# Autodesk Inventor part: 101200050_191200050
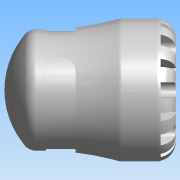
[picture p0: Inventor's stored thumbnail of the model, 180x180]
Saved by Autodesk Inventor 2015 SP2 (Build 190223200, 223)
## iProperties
Created: 2016-12
Part Number: 101200050_191200050
Material: PVC-Piping
Description: PLASSON END PLUG 50 SERIES 1
Document SubType Name: Modeling
Designer: KIM
Mass: 57.8335 g
Surface Area: 121.129 cm^2
Volume: 41.3096 cm^3
Density: 1.4 g/cm^3
Appearance: Smooth - White
Author: KIM
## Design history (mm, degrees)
derived "1012.ipt"
feature "Solid1::1012.ipt"
tag "TaggingFeature1"
body "Solid1"
other parameters: "d0" = 102, "d1" = 33.18, "d3" = 62.5, "d4" = 85, "d6" = 79, "d7" = 86.9, "d8" = 72.25, "d13" = 9, "d14" = 9, "d15" = 0, "d17" = 360 deg, "d19" = 8 deg, "d20" = 1, "d21" = 1, "d22" = 8 deg, "d24" = 0, "d26" = 360 deg, "d32" = 8.5, "d33" = 8.5, "d34" = 11, "d35" = 17.5, "d36" = 17.64, "d37" = 0, "d42" = 360 deg, "d45" = 14.875, "d46" = 1, "d48" = 0, "d49" = 0.85, "E_" = 85, "H_" = 102, "l_" = 79, "d9" = 11.25, "d11" = 85, "d12" = 62.5
